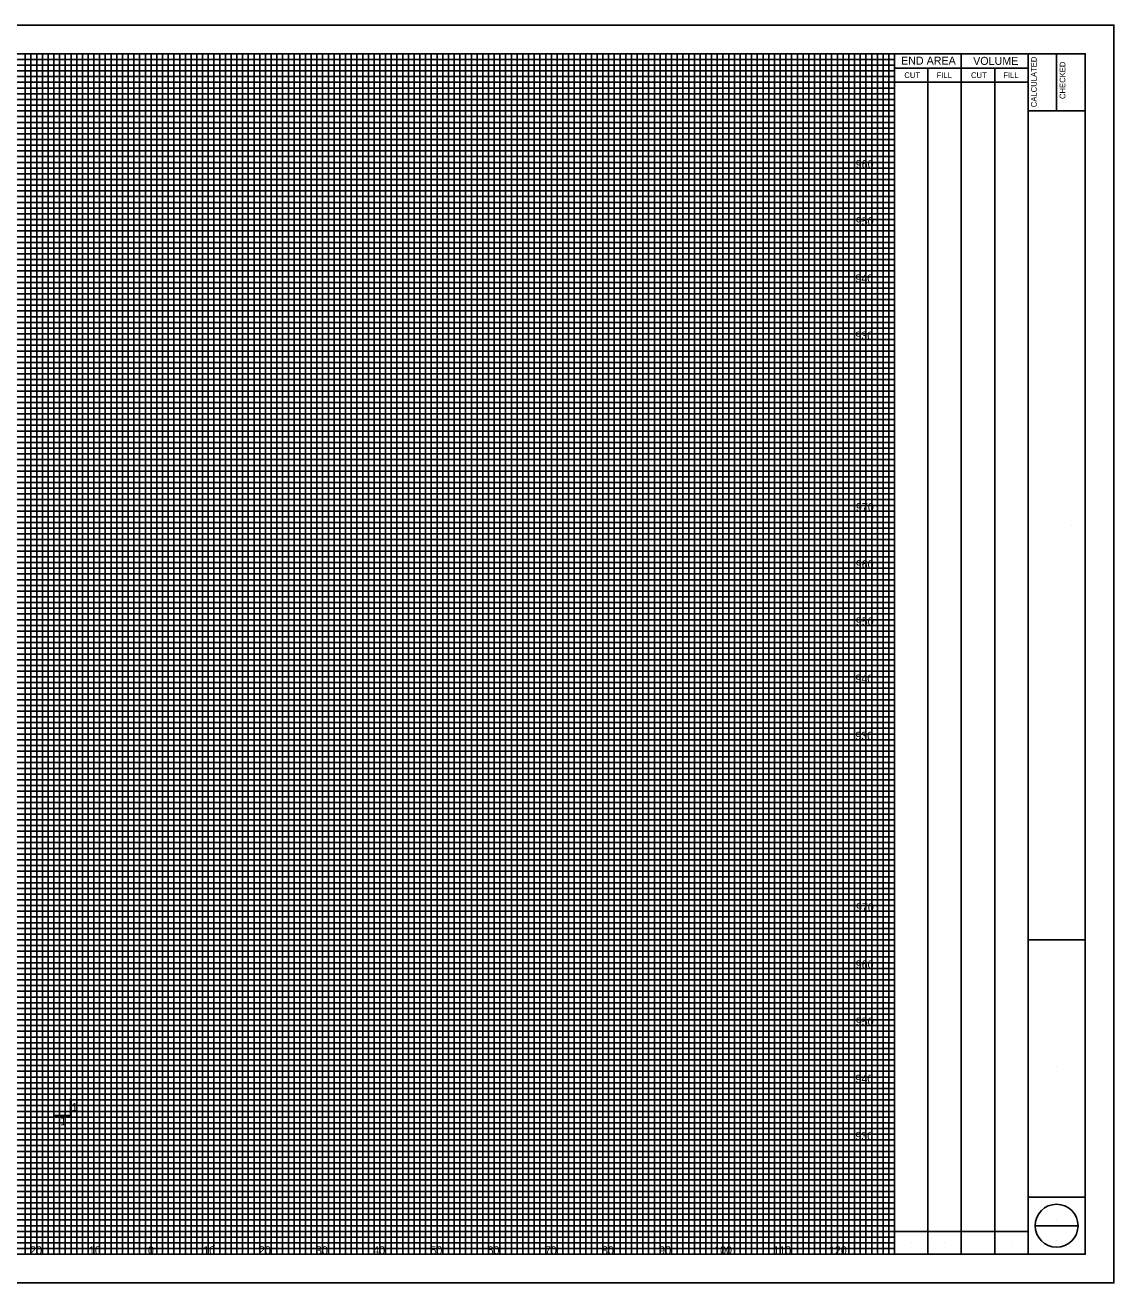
# Model space of a CAD drawing. Extents: x -62 to 340, y 0 to 220.
# Drawn here: x 149.6 to 340, y 0 to 220 of the extents above; entities that cross this region are included whole.
import ezdxf

# ---------------------------------------------------------------- set-up
doc = ezdxf.new("R2010")
doc.units = 0
for name, color, linetype in [('SH_Border', 7, 'Continuous'), ('SH_Cut_Line', 7, 'Continuous'), ('SH_Data', 7, 'Continuous'), ('SH_Major_Grid_Line', 7, 'Continuous'), ('SH_Minor_Grid_Line', 7, 'Continuous'), ('XS_P_Annotation', 7, 'Continuous')]:
    doc.layers.add(name, color=color, linetype=linetype)

msp = doc.modelspace()

# ---------------------------------------------------------------- linework, layer by layer
at = {"layer": 'SH_Border'}
for p, q in [((325, 5), (325, 215)), ((330, 215), (330, 205)), ((325, 205), (335, 205)), ((325, 60), (335, 60)), ((325, 15), (335, 15))]:
    msp.add_line(p, q, dxfattribs=at)
msp.add_lwpolyline([(20, 215), (335, 215), (335, 5), (20, 5)], close=True, dxfattribs=at)
at = {"layer": 'SH_Cut_Line'}
msp.add_lwpolyline([(0, 0), (340, 0), (340, 220), (0, 220)], close=True, dxfattribs=at)
at = {"layer": 'SH_Data'}
for p, q in [((301.66, 5), (301.66, 215)), ((313.33, 5), (313.33, 215)), ((301.66, 212.5), (325, 212.5)), ((307.5, 5), (307.5, 212.5)), ((319.17, 5), (319.17, 212.5)), ((301.66, 210), (325, 210)), ((329.2, 210.04), (329.2, 210.04)), ((334.2, 210.04), (334.2, 210.04)), ((327.5, 132.5), (327.5, 132.5)), ((332.52, 132.5), (332.52, 132.5)), ((330, 37.92), (330, 37.92)), ((301.66, 9), (325, 9)), ((326.25, 10), (333.75, 10)), ((330, 10.85), (330, 10.85)), ((304.58, 7), (304.58, 7)), ((310.42, 7), (310.42, 7)), ((316.25, 7), (316.25, 7)), ((322.08, 7), (322.08, 7)), ((330, 7.45), (330, 7.45))]:
    msp.add_line(p, q, dxfattribs=at)
msp.add_circle((330, 10), 3.75, dxfattribs=at)
at = {"layer": 'SH_Major_Grid_Line'}
for p, q in [((151.66, 5), (151.66, 215)), ((161.66, 5), (161.66, 215)), ((171.66, 5), (171.66, 215)), ((181.66, 5), (181.66, 215)), ((191.66, 5), (191.66, 215)), ((201.66, 5), (201.66, 215)), ((211.66, 5), (211.66, 215)), ((221.66, 5), (221.66, 215)), ((231.66, 5), (231.66, 215)), ((241.66, 5), (241.66, 215)), ((251.66, 5), (251.66, 215)), ((261.66, 5), (261.66, 215)), ((271.66, 5), (271.66, 215)), ((281.66, 5), (281.66, 215)), ((291.66, 5), (291.66, 215)), ((31.66, 205), (301.66, 205)), ((31.66, 195), (301.66, 195)), ((31.66, 185), (301.66, 185)), ((31.66, 175), (301.66, 175)), ((31.66, 165), (301.66, 165)), ((31.66, 155), (301.66, 155)), ((31.66, 145), (301.66, 145)), ((31.66, 135), (301.66, 135)), ((31.66, 125), (301.66, 125)), ((31.66, 115), (301.66, 115)), ((31.66, 105), (301.66, 105)), ((31.66, 95), (301.66, 95)), ((31.66, 85), (301.66, 85)), ((31.66, 75), (301.66, 75)), ((31.66, 65), (301.66, 65)), ((31.66, 55), (301.66, 55)), ((31.66, 45), (301.66, 45)), ((31.66, 35), (301.66, 35)), ((31.66, 25), (301.66, 25)), ((31.66, 15), (301.66, 15))]:
    msp.add_line(p, q, dxfattribs=at)
at = {"layer": 'SH_Minor_Grid_Line'}
for p, q in [((31.66, 214), (301.66, 214)), ((149.66, 5), (149.66, 215)), ((150.66, 5), (150.66, 215)), ((152.66, 5), (152.66, 215)), ((153.66, 5), (153.66, 215)), ((154.66, 5), (154.66, 215)), ((155.66, 5), (155.66, 215)), ((156.66, 5), (156.66, 215)), ((157.66, 5), (157.66, 215)), ((158.66, 5), (158.66, 215)), ((159.66, 5), (159.66, 215)), ((160.66, 5), (160.66, 215)), ((162.66, 5), (162.66, 215)), ((163.66, 5), (163.66, 215)), ((164.66, 5), (164.66, 215)), ((165.66, 5), (165.66, 215)), ((166.66, 5), (166.66, 215)), ((167.66, 5), (167.66, 215)), ((168.66, 5), (168.66, 215)), ((169.66, 5), (169.66, 215)), ((170.66, 5), (170.66, 215)), ((172.66, 5), (172.66, 215)), ((173.66, 5), (173.66, 215)), ((174.66, 5), (174.66, 215)), ((175.66, 5), (175.66, 215)), ((176.66, 5), (176.66, 215)), ((177.66, 5), (177.66, 215)), ((178.66, 5), (178.66, 215)), ((179.66, 5), (179.66, 215)), ((180.66, 5), (180.66, 215)), ((182.66, 5), (182.66, 215)), ((183.66, 5), (183.66, 215)), ((184.66, 5), (184.66, 215)), ((185.66, 5), (185.66, 215)), ((186.66, 5), (186.66, 215)), ((187.66, 5), (187.66, 215)), ((188.66, 5), (188.66, 215)), ((189.66, 5), (189.66, 215)), ((190.66, 5), (190.66, 215)), ((192.66, 5), (192.66, 215)), ((193.66, 5), (193.66, 215)), ((194.66, 5), (194.66, 215)), ((195.66, 5), (195.66, 215)), ((196.66, 5), (196.66, 215)), ((197.66, 5), (197.66, 215)), ((198.66, 5), (198.66, 215)), ((199.66, 5), (199.66, 215)), ((200.66, 5), (200.66, 215)), ((202.66, 5), (202.66, 215)), ((203.66, 5), (203.66, 215)), ((204.66, 5), (204.66, 215)), ((205.66, 5), (205.66, 215)), ((206.66, 5), (206.66, 215)), ((207.66, 5), (207.66, 215)), ((208.66, 5), (208.66, 215)), ((209.66, 5), (209.66, 215)), ((210.66, 5), (210.66, 215)), ((212.66, 5), (212.66, 215)), ((213.66, 5), (213.66, 215)), ((214.66, 5), (214.66, 215)), ((215.66, 5), (215.66, 215)), ((216.66, 5), (216.66, 215)), ((217.66, 5), (217.66, 215)), ((218.66, 5), (218.66, 215)), ((219.66, 5), (219.66, 215)), ((220.66, 5), (220.66, 215)), ((222.66, 5), (222.66, 215)), ((223.66, 5), (223.66, 215)), ((224.66, 5), (224.66, 215)), ((225.66, 5), (225.66, 215)), ((226.66, 5), (226.66, 215)), ((227.66, 5), (227.66, 215)), ((228.66, 5), (228.66, 215)), ((229.66, 5), (229.66, 215)), ((230.66, 5), (230.66, 215)), ((232.66, 5), (232.66, 215)), ((233.66, 5), (233.66, 215)), ((234.66, 5), (234.66, 215)), ((235.66, 5), (235.66, 215)), ((236.66, 5), (236.66, 215)), ((237.66, 5), (237.66, 215)), ((238.66, 5), (238.66, 215)), ((239.66, 5), (239.66, 215)), ((240.66, 5), (240.66, 215)), ((242.66, 5), (242.66, 215)), ((243.66, 5), (243.66, 215)), ((244.66, 5), (244.66, 215)), ((245.66, 5), (245.66, 215)), ((246.66, 5), (246.66, 215)), ((247.66, 5), (247.66, 215)), ((248.66, 5), (248.66, 215)), ((249.66, 5), (249.66, 215)), ((250.66, 5), (250.66, 215)), ((252.66, 5), (252.66, 215)), ((253.66, 5), (253.66, 215)), ((254.66, 5), (254.66, 215)), ((255.66, 5), (255.66, 215)), ((256.66, 5), (256.66, 215)), ((257.66, 5), (257.66, 215)), ((258.66, 5), (258.66, 215)), ((259.66, 5), (259.66, 215)), ((260.66, 5), (260.66, 215)), ((262.66, 5), (262.66, 215)), ((263.66, 5), (263.66, 215)), ((264.66, 5), (264.66, 215)), ((265.66, 5), (265.66, 215)), ((266.66, 5), (266.66, 215)), ((267.66, 5), (267.66, 215)), ((268.66, 5), (268.66, 215)), ((269.66, 5), (269.66, 215)), ((270.66, 5), (270.66, 215)), ((272.66, 5), (272.66, 215)), ((273.66, 5), (273.66, 215)), ((274.66, 5), (274.66, 215)), ((275.66, 5), (275.66, 215)), ((276.66, 5), (276.66, 215)), ((277.66, 5), (277.66, 215)), ((278.66, 5), (278.66, 215)), ((279.66, 5), (279.66, 215)), ((280.66, 5), (280.66, 215)), ((282.66, 5), (282.66, 215)), ((283.66, 5), (283.66, 215)), ((284.66, 5), (284.66, 215)), ((285.66, 5), (285.66, 215)), ((286.66, 5), (286.66, 215)), ((287.66, 5), (287.66, 215)), ((288.66, 5), (288.66, 215)), ((289.66, 5), (289.66, 215)), ((290.66, 5), (290.66, 215)), ((292.66, 5), (292.66, 215)), ((293.66, 5), (293.66, 215)), ((294.66, 5), (294.66, 215)), ((295.66, 5), (295.66, 215)), ((296.66, 5), (296.66, 215)), ((297.66, 5), (297.66, 215)), ((298.66, 5), (298.66, 215)), ((299.66, 5), (299.66, 215)), ((300.66, 5), (300.66, 215)), ((31.66, 213), (301.66, 213)), ((31.66, 212), (301.66, 212)), ((31.66, 211), (301.66, 211)), ((31.66, 210), (301.66, 210)), ((31.66, 209), (301.66, 209)), ((31.66, 208), (301.66, 208)), ((31.66, 207), (301.66, 207)), ((31.66, 206), (301.66, 206)), ((31.66, 204), (301.66, 204)), ((31.66, 203), (301.66, 203)), ((31.66, 202), (301.66, 202)), ((31.66, 201), (301.66, 201)), ((31.66, 200), (301.66, 200)), ((31.66, 199), (301.66, 199)), ((31.66, 198), (301.66, 198)), ((31.66, 197), (301.66, 197)), ((31.66, 196), (301.66, 196)), ((31.66, 194), (301.66, 194)), ((31.66, 193), (301.66, 193)), ((31.66, 192), (301.66, 192)), ((31.66, 191), (301.66, 191)), ((31.66, 190), (301.66, 190)), ((31.66, 189), (301.66, 189)), ((31.66, 188), (301.66, 188)), ((31.66, 187), (301.66, 187)), ((31.66, 186), (301.66, 186)), ((31.66, 184), (301.66, 184)), ((31.66, 183), (301.66, 183)), ((31.66, 182), (301.66, 182)), ((31.66, 181), (301.66, 181)), ((31.66, 180), (301.66, 180)), ((31.66, 179), (301.66, 179)), ((31.66, 178), (301.66, 178)), ((31.66, 177), (301.66, 177)), ((31.66, 176), (301.66, 176)), ((31.66, 174), (301.66, 174)), ((31.66, 173), (301.66, 173)), ((31.66, 172), (301.66, 172)), ((31.66, 171), (301.66, 171)), ((31.66, 170), (301.66, 170)), ((31.66, 169), (301.66, 169)), ((31.66, 168), (301.66, 168)), ((31.66, 167), (301.66, 167)), ((31.66, 166), (301.66, 166)), ((31.66, 164), (301.66, 164)), ((31.66, 163), (301.66, 163)), ((31.66, 162), (301.66, 162)), ((31.66, 161), (301.66, 161)), ((31.66, 160), (301.66, 160)), ((31.66, 159), (301.66, 159)), ((31.66, 158), (301.66, 158)), ((31.66, 157), (301.66, 157)), ((31.66, 156), (301.66, 156)), ((31.66, 154), (301.66, 154)), ((31.66, 153), (301.66, 153)), ((31.66, 152), (301.66, 152)), ((31.66, 151), (301.66, 151)), ((31.66, 150), (301.66, 150)), ((31.66, 149), (301.66, 149)), ((31.66, 148), (301.66, 148)), ((31.66, 147), (301.66, 147)), ((31.66, 146), (301.66, 146)), ((31.66, 144), (301.66, 144)), ((31.66, 143), (301.66, 143)), ((31.66, 142), (301.66, 142)), ((31.66, 141), (301.66, 141)), ((31.66, 140), (301.66, 140)), ((31.66, 139), (301.66, 139)), ((31.66, 138), (301.66, 138)), ((31.66, 137), (301.66, 137)), ((31.66, 136), (301.66, 136)), ((31.66, 134), (301.66, 134)), ((31.66, 133), (301.66, 133)), ((31.66, 132), (301.66, 132)), ((31.66, 131), (301.66, 131)), ((31.66, 130), (301.66, 130)), ((31.66, 129), (301.66, 129)), ((31.66, 128), (301.66, 128)), ((31.66, 127), (301.66, 127)), ((31.66, 126), (301.66, 126)), ((31.66, 124), (301.66, 124)), ((31.66, 123), (301.66, 123)), ((31.66, 122), (301.66, 122)), ((31.66, 121), (301.66, 121)), ((31.66, 120), (301.66, 120)), ((31.66, 119), (301.66, 119)), ((31.66, 118), (301.66, 118)), ((31.66, 117), (301.66, 117)), ((31.66, 116), (301.66, 116)), ((31.66, 114), (301.66, 114)), ((31.66, 113), (301.66, 113)), ((31.66, 112), (301.66, 112)), ((31.66, 111), (301.66, 111)), ((31.66, 110), (301.66, 110)), ((31.66, 109), (301.66, 109)), ((31.66, 108), (301.66, 108)), ((31.66, 107), (301.66, 107)), ((31.66, 106), (301.66, 106)), ((31.66, 104), (301.66, 104)), ((31.66, 103), (301.66, 103)), ((31.66, 102), (301.66, 102)), ((31.66, 101), (301.66, 101)), ((31.66, 100), (301.66, 100)), ((31.66, 99), (301.66, 99)), ((31.66, 98), (301.66, 98)), ((31.66, 97), (301.66, 97)), ((31.66, 96), (301.66, 96)), ((31.66, 94), (301.66, 94)), ((31.66, 93), (301.66, 93)), ((31.66, 92), (301.66, 92)), ((31.66, 91), (301.66, 91)), ((31.66, 90), (301.66, 90)), ((31.66, 89), (301.66, 89)), ((31.66, 88), (301.66, 88)), ((31.66, 87), (301.66, 87)), ((31.66, 86), (301.66, 86)), ((31.66, 84), (301.66, 84)), ((31.66, 83), (301.66, 83)), ((31.66, 82), (301.66, 82)), ((31.66, 81), (301.66, 81)), ((31.66, 80), (301.66, 80)), ((31.66, 79), (301.66, 79)), ((31.66, 78), (301.66, 78)), ((31.66, 77), (301.66, 77)), ((31.66, 76), (301.66, 76)), ((31.66, 74), (301.66, 74)), ((31.66, 73), (301.66, 73)), ((31.66, 72), (301.66, 72)), ((31.66, 71), (301.66, 71)), ((31.66, 70), (301.66, 70)), ((31.66, 69), (301.66, 69)), ((31.66, 68), (301.66, 68)), ((31.66, 67), (301.66, 67)), ((31.66, 66), (301.66, 66)), ((31.66, 64), (301.66, 64)), ((31.66, 63), (301.66, 63)), ((31.66, 62), (301.66, 62)), ((31.66, 61), (301.66, 61)), ((31.66, 60), (301.66, 60)), ((31.66, 59), (301.66, 59)), ((31.66, 58), (301.66, 58)), ((31.66, 57), (301.66, 57)), ((31.66, 56), (301.66, 56)), ((31.66, 54), (301.66, 54)), ((31.66, 53), (301.66, 53)), ((31.66, 52), (301.66, 52)), ((31.66, 51), (301.66, 51)), ((31.66, 50), (301.66, 50)), ((31.66, 49), (301.66, 49)), ((31.66, 48), (301.66, 48)), ((31.66, 47), (301.66, 47)), ((31.66, 46), (301.66, 46)), ((31.66, 44), (301.66, 44)), ((31.66, 43), (301.66, 43)), ((31.66, 42), (301.66, 42)), ((31.66, 41), (301.66, 41)), ((31.66, 40), (301.66, 40)), ((31.66, 39), (301.66, 39)), ((31.66, 38), (301.66, 38)), ((31.66, 37), (301.66, 37)), ((31.66, 36), (301.66, 36)), ((31.66, 34), (301.66, 34)), ((31.66, 33), (301.66, 33)), ((31.66, 32), (301.66, 32)), ((31.66, 31), (301.66, 31)), ((31.66, 30), (301.66, 30)), ((31.66, 29), (301.66, 29)), ((31.66, 28), (301.66, 28)), ((31.66, 27), (301.66, 27)), ((31.66, 26), (301.66, 26)), ((31.66, 24), (301.66, 24)), ((31.66, 23), (301.66, 23)), ((31.66, 22), (301.66, 22)), ((31.66, 21), (301.66, 21)), ((31.66, 20), (301.66, 20)), ((31.66, 19), (301.66, 19)), ((31.66, 18), (301.66, 18)), ((31.66, 17), (301.66, 17)), ((31.66, 16), (301.66, 16)), ((31.66, 14), (301.66, 14)), ((31.66, 13), (301.66, 13)), ((31.66, 12), (301.66, 12)), ((31.66, 11), (301.66, 11)), ((31.66, 10), (301.66, 10)), ((31.66, 9), (301.66, 9)), ((31.66, 8), (301.66, 8)), ((31.66, 7), (301.66, 7)), ((31.66, 6), (301.66, 6))]:
    msp.add_line(p, q, dxfattribs=at)
at = {"layer": 'XS_P_Annotation'}
msp.add_lwpolyline([(154.56, 29.26), (157.56, 29.26), (157.56, 32.26)], dxfattribs=at)

# ---------------------------------------------------------------- texts
at = {"layer": 'SH_Data'}
for s, height, p in [('END AREA', 1.4, (302.79, 213.09)), ('VOLUME', 1.4, (315.4, 213.05)), ('CUT', 1, (303.37, 210.75)), ('FILL', 1, (309, 210.75)), ('CUT', 1, (315.03, 210.75)), ('FILL', 1, (320.67, 210.75))]:
    msp.add_text(s, height=height, dxfattribs=at).set_placement(p)
for s, p in [('CALCULATED', (326.52, 205.65)), ('CHECKED', (331.52, 207.08))]:
    msp.add_text(s, height=1, rotation=90, dxfattribs=at).set_placement(p)
at = {"layer": 'XS_P_Annotation'}
for s, p in [('960', (294.87, 195)), ('950', (294.88, 185)), ('940', (294.81, 175)), ('930', (294.8, 165)), ('970', (294.9, 135)), ('960', (294.87, 125)), ('950', (294.88, 115)), ('940', (294.81, 105)), ('930', (294.8, 95)), ('970', (294.9, 65)), ('960', (294.87, 55)), ('950', (294.88, 45)), ('940', (294.81, 35)), ('1', (157.77, 30.06)), ('1', (155.77, 27.56)), ('930', (294.8, 25)), ('20', (150.51, 5)), ('10', (160.78, 5)), ('0', (171.11, 5)), ('10', (180.78, 5)), ('20', (190.51, 5)), ('30', (200.49, 5)), ('40', (210.5, 5)), ('50', (220.5, 5)), ('60', (230.49, 5)), ('70', (240.51, 5)), ('80', (250.5, 5)), ('90', (260.49, 5)), ('100', (270.11, 5)), ('110', (280.45, 5)), ('120', (290.18, 5))]:
    msp.add_text(s, height=1.4, dxfattribs=at).set_placement(p)

doc.saveas('drawing.dxf')
